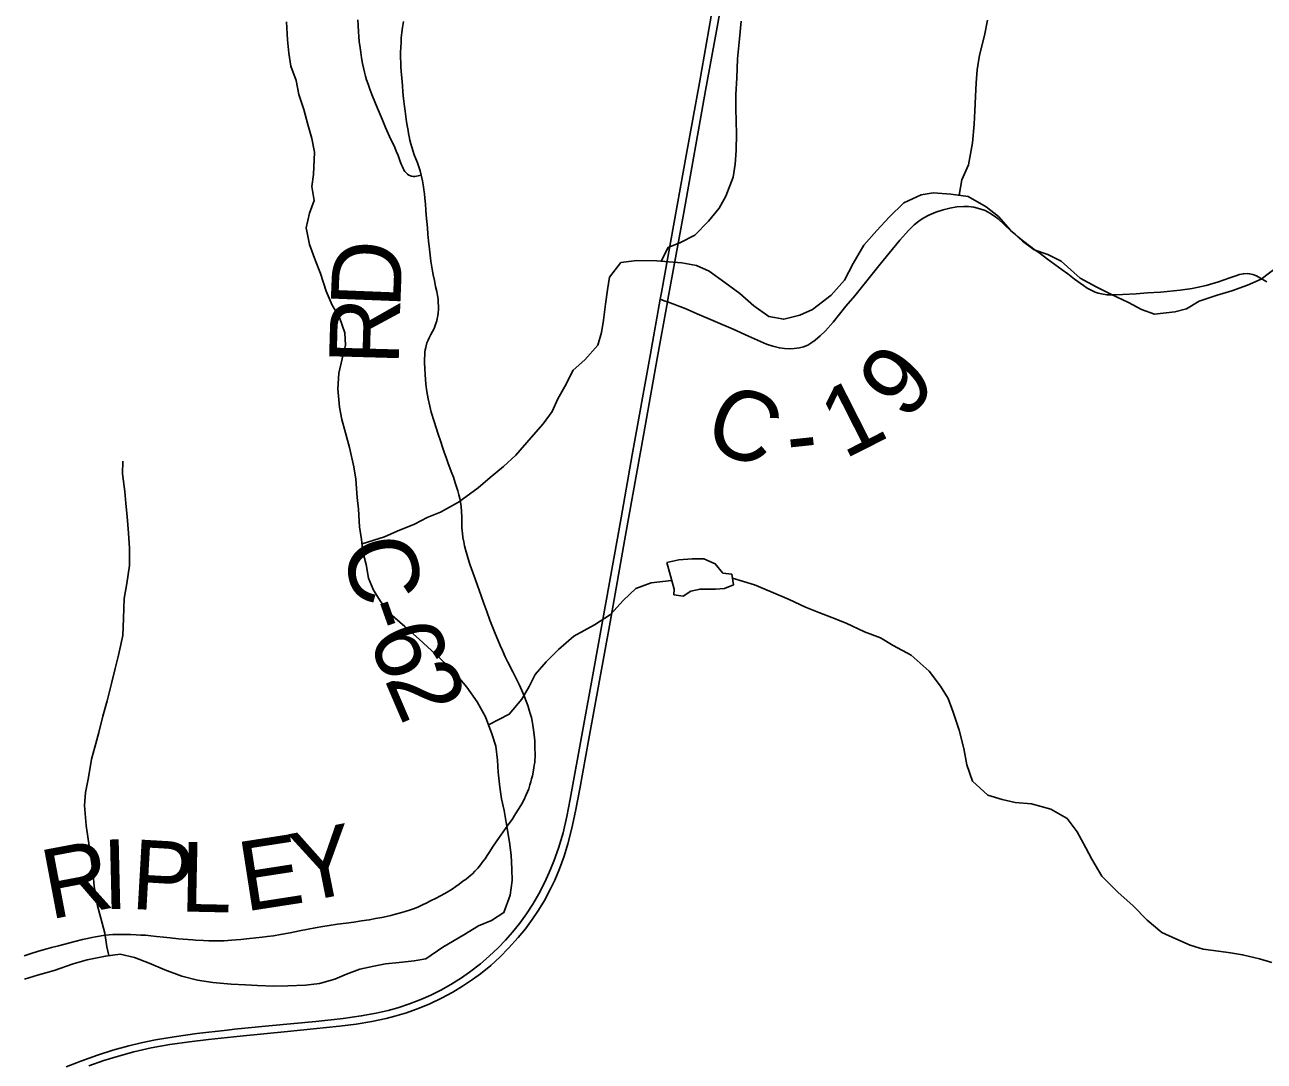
# Model space of a CAD drawing. Extents: x 0 to 34, y 0 to 22.
# Drawn here: x 6.359 to 7.37, y 18.618 to 19.464 of the extents above; entities that cross this region are included whole.
import ezdxf

# ---------------------------------------------------------------- set-up
doc = ezdxf.new("R2010")
doc.units = 0
for name, color, linetype in [('GM_X_County_Road', 7, 'Continuous'), ('GM_X_County_Road_Text', 7, 'Continuous'), ('GM_X_Minor_Lake', 7, 'Continuous'), ('GM_X_Minor_River', 7, 'Continuous'), ('GM_X_Township_Road', 7, 'Continuous'), ('GM_X_US_Route', 7, 'Continuous')]:
    doc.layers.add(name, color=color, linetype=linetype)

msp = doc.modelspace()

# ---------------------------------------------------------------- linework, layer by layer
at = {"layer": 'GM_X_County_Road'}
for points in [[(6.6827, 19.3412), (6.6818, 19.3448), (6.6808, 19.3479), (6.6796, 19.3511), (6.6783, 19.3545), (6.677, 19.3576), (6.676, 19.3605), (6.6749, 19.3639), (6.6742, 19.3668), (6.6735, 19.3696), (6.6729, 19.3726), (6.6724, 19.3751), (6.6719, 19.3776), (6.6711, 19.3816), (6.6706, 19.3847), (6.67, 19.3891), (6.6695, 19.3933), (6.669, 19.3973), (6.6683, 19.4037), (6.6678, 19.4089), (6.6673, 19.4144), (6.6668, 19.4204), (6.6664, 19.426), (6.6661, 19.4295), (6.666, 19.4329), (6.6659, 19.4371), (6.6659, 19.4414), (6.666, 19.4454), (6.6662, 19.4497), (6.6664, 19.4533), (6.6668, 19.4575), (6.6674, 19.4617), (6.6683, 19.4666)], [(6.4965, 18.7171), (6.4987, 18.7169), (6.5051, 18.7166), (6.5095, 18.7164), (6.5136, 18.7164), (6.5178, 18.7164), (6.522, 18.7165), (6.5279, 18.7169), (6.5355, 18.7175), (6.5427, 18.7182), (6.5478, 18.7188), (6.5529, 18.7193), (6.5571, 18.7199), (6.5622, 18.7206), (6.5678, 18.7215), (6.5757, 18.723), (6.5834, 18.7245), (6.5906, 18.7259), (6.5963, 18.727), (6.6025, 18.7281), (6.6075, 18.7289), (6.6145, 18.7299), (6.6216, 18.7308), (6.6277, 18.7317), (6.634, 18.7326), (6.6403, 18.7335), (6.6455, 18.7345), (6.6505, 18.7354), (6.6544, 18.7363), (6.6579, 18.7371), (6.6617, 18.7381), (6.6659, 18.7392), (6.6696, 18.7403), (6.6738, 18.7417), (6.6771, 18.7429), (6.6804, 18.7442), (6.6837, 18.7458), (6.6868, 18.7472), (6.6909, 18.7492), (6.6942, 18.7509), (6.6984, 18.7531), (6.7018, 18.755), (6.7051, 18.7569), (6.7079, 18.7586), (6.7108, 18.7607), (6.7136, 18.7626), (6.7167, 18.765), (6.7192, 18.7668), (6.7216, 18.7687), (6.7244, 18.7711), (6.7265, 18.7732), (6.7288, 18.7756), (6.7311, 18.7784), (6.733, 18.781), (6.7347, 18.7834), (6.7364, 18.7859), (6.7386, 18.7892), (6.7409, 18.7928), (6.7444, 18.798), (6.7475, 18.8026), (6.7515, 18.808), (6.7542, 18.8118), (6.7568, 18.8155), (6.7596, 18.8199), (6.7626, 18.8247), (6.7646, 18.8281), (6.7665, 18.8317), (6.7681, 18.835), (6.7694, 18.838), (6.7703, 18.8405), (6.7713, 18.8436), (6.772, 18.8461), (6.7727, 18.8485), (6.7733, 18.851), (6.774, 18.854), (6.7746, 18.8575), (6.7749, 18.8597), (6.7752, 18.862), (6.7754, 18.864), (6.7756, 18.8663), (6.7756, 18.8695), (6.7754, 18.8728), (6.7753, 18.8761), (6.7752, 18.8795), (6.7747, 18.8846), (6.7742, 18.8886), (6.7738, 18.8924), (6.7732, 18.8957), (6.7725, 18.8987), (6.7716, 18.902), (6.7708, 18.9047), (6.7698, 18.9076), (6.7687, 18.9105), (6.7677, 18.9133), (6.7665, 18.9164), (6.7648, 18.9206), (6.7626, 18.9255), (6.7604, 18.93), (6.7575, 18.936), (6.7533, 18.9437), (6.7512, 18.9482), (6.7489, 18.9532), (6.747, 18.9575), (6.7452, 18.962), (6.743, 18.9673), (6.7409, 18.9726), (6.7387, 18.9781), (6.7361, 18.9851), (6.7337, 18.9916), (6.7315, 18.9979), (6.7268, 19.0109), (6.7247, 19.017), (6.7226, 19.0229), (6.721, 19.0282), (6.7198, 19.0319), (6.7187, 19.0356), (6.718, 19.0386), (6.7173, 19.0419), (6.7167, 19.0455), (6.7164, 19.0489), (6.7159, 19.0532), (6.7158, 19.0578), (6.7157, 19.0622), (6.7155, 19.0667), (6.7152, 19.0707), (6.7146, 19.0744), (6.7141, 19.0772), (6.7133, 19.0804), (6.7124, 19.0835), (6.7115, 19.0868), (6.7104, 19.0901), (6.7089, 19.0946), (6.7077, 19.098), (6.7064, 19.1016), (6.7045, 19.1067), (6.703, 19.1109), (6.7017, 19.1143), (6.7003, 19.1183), (6.6984, 19.1243), (6.6966, 19.1297), (6.6949, 19.1349), (6.6932, 19.1402), (6.6909, 19.1478), (6.6896, 19.1526), (6.6883, 19.1587), (6.6873, 19.1647), (6.6865, 19.1707), (6.6858, 19.1786), (6.6855, 19.1834), (6.6853, 19.188), (6.6853, 19.1916), (6.6855, 19.1944), (6.6857, 19.1968), (6.6859, 19.1987), (6.6863, 19.2004), (6.6867, 19.2019), (6.6873, 19.2042), (6.6883, 19.2066), (6.6891, 19.2084), (6.6905, 19.211), (6.6919, 19.2136), (6.6931, 19.2161), (6.6941, 19.2184), (6.6947, 19.2202), (6.6953, 19.2222), (6.6957, 19.2241), (6.6961, 19.2264), (6.6965, 19.2288), (6.6967, 19.2314), (6.6968, 19.2343), (6.6966, 19.2372), (6.6964, 19.2399), (6.6959, 19.243), (6.6953, 19.2461), (6.6944, 19.2504), (6.6934, 19.2552), (6.6924, 19.2598), (6.6918, 19.2629), (6.6912, 19.2661), (6.6905, 19.271), (6.6899, 19.2758), (6.6893, 19.2807), (6.6886, 19.2876), (6.6881, 19.2929), (6.6877, 19.2981), (6.6873, 19.3032), (6.6868, 19.3084), (6.6865, 19.3127), (6.6862, 19.3175), (6.6857, 19.3223), (6.6853, 19.3258), (6.6849, 19.3291), (6.6845, 19.3315), (6.6836, 19.3366), (6.6827, 19.3412)], [(7.0642, 19.2775), (7.0729, 19.2881), (7.08, 19.2961), (7.0845, 19.3005), (7.0884, 19.3036), (7.0921, 19.3061), (7.0966, 19.3084), (7.1024, 19.3109), (7.1083, 19.3129), (7.1138, 19.3142), (7.1194, 19.3152), (7.1251, 19.3156), (7.1289, 19.3156), (7.1333, 19.315), (7.1382, 19.3137), (7.1424, 19.3122), (7.1464, 19.3102), (7.1501, 19.3078), (7.1531, 19.3054), (7.1631, 19.2961), (7.1673, 19.2926), (7.1687, 19.2914), (7.174, 19.2871), (7.1833, 19.28), (7.1873, 19.2771), (7.1933, 19.2726), (7.1963, 19.2704), (7.2023, 19.266), (7.2053, 19.2638), (7.2098, 19.2605), (7.2153, 19.2564), (7.2228, 19.251), (7.2258, 19.249), (7.2323, 19.2457), (7.2346, 19.2449), (7.2375, 19.2442), (7.2417, 19.2435), (7.2484, 19.2434), (7.2545, 19.2437), (7.2657, 19.2444), (7.275, 19.245), (7.2855, 19.2458), (7.3015, 19.2472), (7.3113, 19.2486), (7.3227, 19.2511), (7.3327, 19.2541), (7.3421, 19.2574), (7.3462, 19.2588), (7.35, 19.26), (7.3531, 19.2607), (7.3561, 19.2608), (7.3581, 19.2607), (7.3607, 19.26), (7.3638, 19.2589), (7.3666, 19.2573), (7.3721, 19.2541)], [(6.8834, 19.2378), (6.8979, 19.2323), (6.9077, 19.228), (6.937, 19.2154), (6.9495, 19.2098), (6.9642, 19.2033), (6.9694, 19.2015), (6.9747, 19.2002), (6.979, 19.1996), (6.9832, 19.1994), (6.9868, 19.1996), (6.991, 19.2003), (6.9945, 19.2012), (6.9978, 19.2025), (7.0004, 19.204), (7.0038, 19.2065), (7.008, 19.21), (7.0124, 19.2142), (7.0185, 19.2212), (7.029, 19.2342), (7.0362, 19.2427), (7.0471, 19.2563), (7.0568, 19.2684), (7.0642, 19.2775)], [(6.8776, 19.2399), (6.8809, 19.2387), (6.8834, 19.2378)], [(6.359, 18.7042), (6.3663, 18.7066), (6.3725, 18.7084), (6.3773, 18.7098), (6.3813, 18.7109), (6.3868, 18.7123), (6.4002, 18.7158), (6.4065, 18.7174), (6.4105, 18.7183), (6.4142, 18.719), (6.4171, 18.7196), (6.4203, 18.7201), (6.4247, 18.7209), (6.4281, 18.7213), (6.4312, 18.7215), (6.4349, 18.7217), (6.4384, 18.7217), (6.4423, 18.7217), (6.4456, 18.7217), (6.4502, 18.7214), (6.454, 18.7211), (6.4578, 18.7209), (6.4623, 18.7205), (6.4669, 18.72), (6.4725, 18.7193), (6.478, 18.7188), (6.4847, 18.7181), (6.4923, 18.7174), (6.4965, 18.7171)]]:
    msp.add_lwpolyline(points, dxfattribs=at)
at = {"layer": 'GM_X_Minor_Lake'}
for points in [[(6.8888, 19.0033), (6.8887, 18.9988), (6.8963, 18.9975), (6.9024, 19.0016), (6.91, 19.0034), (6.9225, 19.0033), (6.9301, 19.0039), (6.9373, 19.0068), (6.9359, 19.0156), (6.9287, 19.0164), (6.9224, 19.0241), (6.913, 19.028), (6.9035, 19.0282), (6.8928, 19.0272), (6.883, 19.025)], [(6.883, 19.025), (6.8888, 19.0033)]]:
    msp.add_lwpolyline(points, dxfattribs=at)
at = {"layer": 'GM_X_Minor_River'}
for points in [[(6.5727, 19.4662), (6.5737, 19.4517), (6.5747, 19.4407), (6.5764, 19.4301), (6.5808, 19.4183), (6.583, 19.4069)], [(6.8784, 19.2709), (6.8839, 19.2821), (6.8942, 19.2862), (6.9057, 19.2921), (6.9168, 19.3037), (6.9257, 19.3142), (6.9311, 19.324), (6.937, 19.3394), (6.9386, 19.35), (6.9395, 19.3614), (6.9397, 19.3751), (6.9394, 19.3849), (6.9392, 19.3959), (6.9393, 19.4069), (6.9399, 19.4206), (6.9405, 19.4361), (6.9422, 19.4524), (6.9435, 19.4668)], [(7.1212, 19.3247), (7.1235, 19.3373), (7.1289, 19.3497), (7.1322, 19.3675), (7.1335, 19.3827), (7.134, 19.3936), (7.1346, 19.4054), (7.1351, 19.4164), (7.136, 19.427), (7.138, 19.4391), (7.142, 19.455), (7.1444, 19.4675)], [(6.583, 19.4069), (6.587, 19.3947), (6.5902, 19.3825), (6.5935, 19.3711), (6.5956, 19.36), (6.5947, 19.3418), (6.5934, 19.332), (6.5955, 19.3206), (6.5916, 19.31), (6.5888, 19.2983), (6.5917, 19.2846), (6.5964, 19.2713), (6.6005, 19.261), (6.6052, 19.2465), (6.61, 19.2351), (6.6159, 19.2251), (6.6203, 19.2126), (6.621, 19.2023), (6.6182, 19.1913), (6.6154, 19.1796), (6.6148, 19.1667), (6.6161, 19.1519), (6.6179, 19.1417), (6.6208, 19.131), (6.6241, 19.1188), (6.6277, 19.1032), (6.6294, 19.093), (6.6304, 19.0782), (6.6314, 19.0687), (6.6324, 19.0542), (6.6341, 19.044), (6.6351, 19.0337), (6.6377, 19.0235), (6.6398, 19.0124), (6.6438, 19.0025), (6.6498, 18.993), (6.6572, 18.9834), (6.6692, 18.973), (6.6809, 18.9626), (6.6947, 18.9499), (6.7078, 18.9376), (6.7198, 18.9234), (6.7284, 18.9115), (6.735, 18.8993), (6.7402, 18.8852), (6.7435, 18.8752), (6.7448, 18.8639), (6.7455, 18.854), (6.7468, 18.8418), (6.7482, 18.8323), (6.7504, 18.8228), (6.7518, 18.8129), (6.7546, 18.797), (6.756, 18.7863), (6.7566, 18.7749), (6.7569, 18.7655), (6.7552, 18.7537), (6.7501, 18.7394), (6.7401, 18.7331), (6.7295, 18.7287), (6.7173, 18.7213), (6.7004, 18.7112), (6.6863, 18.7016), (6.6768, 18.7002), (6.6647, 18.6988), (6.6536, 18.6975), (6.6441, 18.6957), (6.6327, 18.6932), (6.6217, 18.6892), (6.6122, 18.6851), (6.5996, 18.6815), (6.5882, 18.6802), (6.5738, 18.6796), (6.5624, 18.6794), (6.5492, 18.6799), (6.5393, 18.6805), (6.5276, 18.681), (6.5128, 18.6823), (6.5003, 18.6844), (6.4875, 18.6876), (6.4735, 18.6927), (6.4607, 18.6982), (6.449, 18.7029), (6.4373, 18.7054), (6.4251, 18.704), (6.4103, 18.7008), (6.3989, 18.6975), (6.3833, 18.6921), (6.3699, 18.6884), (6.3593, 18.6852)], [(6.6345, 19.0404), (6.6527, 19.046), (6.663, 19.0508), (6.6771, 19.0563), (6.6874, 19.0618), (6.6985, 19.0662), (6.713, 19.0744), (6.729, 19.0859), (6.739, 19.0945), (6.7497, 19.1035), (6.7597, 19.1128), (6.7724, 19.127), (6.782, 19.1383), (6.7894, 19.1484), (6.794, 19.1586), (6.7999, 19.1688), (6.8065, 19.1819), (6.816, 19.1905), (6.8268, 19.2025), (6.8296, 19.2127), (6.8312, 19.2229), (6.8329, 19.2358), (6.8346, 19.2476), (6.8362, 19.2578), (6.8455, 19.2698), (6.8584, 19.2715), (6.8747, 19.2713), (6.8845, 19.2704), (6.8951, 19.2695), (6.9072, 19.2674), (6.9174, 19.2627), (6.9302, 19.2535), (6.9426, 19.2446), (6.9538, 19.2345), (6.9662, 19.2257), (6.9783, 19.2236), (6.9913, 19.2268), (7.0016, 19.2316), (7.0169, 19.2432), (7.0277, 19.2555), (7.035, 19.2691), (7.0436, 19.2841), (7.0543, 19.2961), (7.0643, 19.307), (7.0762, 19.3186), (7.0903, 19.3252), (7.1002, 19.3266), (7.1146, 19.3256), (7.1286, 19.3236), (7.1433, 19.3154), (7.1534, 19.3073), (7.1631, 19.2962), (7.1729, 19.2873), (7.1826, 19.2803), (7.1936, 19.2764), (7.2045, 19.2709), (7.2199, 19.2571), (7.2331, 19.2501), (7.2455, 19.2438), (7.2594, 19.2372), (7.27, 19.2314), (7.2806, 19.2278), (7.2973, 19.2295), (7.3068, 19.232), (7.3171, 19.2383), (7.3316, 19.2431), (7.3437, 19.2467), (7.3563, 19.2514), (7.3677, 19.2562), (7.3811, 19.2667)], [(6.4279, 18.7043), (6.4263, 18.7116), (6.4246, 18.7226), (6.4213, 18.7348), (6.4188, 18.745), (6.416, 18.7606), (6.415, 18.7739), (6.4129, 18.7868), (6.4111, 18.7994), (6.4094, 18.8104), (6.4081, 18.8267), (6.409, 18.8373), (6.4114, 18.8498), (6.4139, 18.8646), (6.4166, 18.8744), (6.4198, 18.8865), (6.423, 18.8997), (6.4266, 18.9122), (6.4302, 18.9265), (6.433, 18.9386), (6.4358, 18.9496), (6.4394, 18.9655), (6.44, 18.9795), (6.4405, 18.9958), (6.4426, 19.0079), (6.4447, 19.0227), (6.4448, 19.0367), (6.4439, 19.0489), (6.4429, 19.0625), (6.4419, 19.0732), (6.4409, 19.083), (6.4392, 19.0975), (6.4393, 19.1077)], [(6.7374, 18.8927), (6.7544, 18.9013), (6.7648, 18.9136), (6.7706, 18.9238), (6.7757, 18.9336), (6.7845, 18.9441), (6.7945, 18.9542), (6.8071, 18.965), (6.8239, 18.9743), (6.8369, 18.9828), (6.8477, 18.9944), (6.8577, 19.0038), (6.8702, 19.0085), (6.8868, 19.0105)], [(6.9364, 19.0123), (6.9544, 19.007), (6.968, 19.0011), (6.9827, 18.9948), (6.9959, 18.9886), (7.0068, 18.9843), (7.0174, 18.9803), (7.0291, 18.9756), (7.0441, 18.9686), (7.0573, 18.9635), (7.0675, 18.9573), (7.0822, 18.9495), (7.0968, 18.9364), (7.1061, 18.9241), (7.1124, 18.9142), (7.1165, 18.9031), (7.1212, 18.8883), (7.1252, 18.8734), (7.1277, 18.8601), (7.1321, 18.8468), (7.1448, 18.8352), (7.1565, 18.8317), (7.1671, 18.8292), (7.1804, 18.8283), (7.1962, 18.8239), (7.2094, 18.8162), (7.2176, 18.8054), (7.2246, 18.7924), (7.2295, 18.7829), (7.2376, 18.7691), (7.2507, 18.756), (7.2631, 18.7449), (7.2747, 18.7333), (7.2867, 18.7233), (7.298, 18.7179), (7.3097, 18.7128), (7.3203, 18.7096), (7.3328, 18.7079), (7.3426, 18.7066), (7.3524, 18.705), (7.3661, 18.7018), (7.3762, 18.6986)]]:
    msp.add_lwpolyline(points, dxfattribs=at)
at = {"layer": 'GM_X_Township_Road'}
msp.add_lwpolyline([(6.6827, 19.3412), (6.6788, 19.3403), (6.6775, 19.3401), (6.6761, 19.3401), (6.6748, 19.3403), (6.6739, 19.3406), (6.6727, 19.3411), (6.6716, 19.3419), (6.6708, 19.3425), (6.67, 19.3433), (6.6693, 19.3442), (6.6686, 19.3454), (6.6679, 19.3467), (6.6673, 19.3479), (6.6667, 19.3495), (6.6655, 19.3524), (6.6638, 19.3572), (6.6623, 19.3607), (6.6611, 19.3637), (6.6567, 19.3728), (6.6536, 19.38), (6.6509, 19.3867), (6.6468, 19.3964), (6.643, 19.4055), (6.6411, 19.4105), (6.6393, 19.4154), (6.6381, 19.419), (6.6373, 19.422), (6.6365, 19.4252), (6.6357, 19.4286), (6.6349, 19.4323), (6.6341, 19.437), (6.6335, 19.4411), (6.6329, 19.445), (6.6322, 19.4501), (6.6318, 19.4544), (6.6315, 19.4581), (6.6312, 19.4632), (6.6311, 19.468)], dxfattribs=at)
at = {"layer": 'GM_X_US_Route'}
for points in [[(6.8834, 19.2378), (6.8838, 19.2398), (6.8967, 19.3106), (6.9145, 19.4102), (6.9234, 19.459), (6.9391, 19.547), (6.9519, 19.6185), (6.9613, 19.6691), (6.9648, 19.6855), (6.9683, 19.6994), (6.9721, 19.7119), (6.9764, 19.7243), (6.9818, 19.7375), (6.9885, 19.7522), (6.996, 19.7673), (7.0027, 19.7793), (7.0075, 19.7871)], [(6.5304, 18.6442), (6.5583, 18.647), (6.5967, 18.6507), (6.619, 18.6531), (6.6338, 18.6551), (6.646, 18.6574), (6.6558, 18.6596), (6.6636, 18.6618), (6.6731, 18.6649), (6.6824, 18.6685), (6.6904, 18.672), (6.6987, 18.6762), (6.7069, 18.6808), (6.7154, 18.6862), (6.722, 18.6908), (6.7309, 18.6977), (6.738, 18.7038), (6.7453, 18.7106), (6.7514, 18.7169), (6.7572, 18.7234), (6.763, 18.7308), (6.7685, 18.7384), (6.7736, 18.7462), (6.7787, 18.7548), (6.7832, 18.7637), (6.7871, 18.7722), (6.7909, 18.7815), (6.7946, 18.7921), (6.7983, 18.8046), (6.8014, 18.8179), (6.8042, 18.832), (6.8237, 18.9395), (6.8456, 19.0616), (6.8547, 19.113), (6.8697, 19.1954), (6.8776, 19.2399), (6.8786, 19.2455), (6.8914, 19.3163), (6.8987, 19.3572), (6.9095, 19.4165), (6.9191, 19.4709)], [(6.5349, 18.6385), (6.5735, 18.6424), (6.6161, 18.6468), (6.6297, 18.6485), (6.6425, 18.6506), (6.654, 18.653), (6.6612, 18.6548), (6.6707, 18.6576), (6.6811, 18.6614), (6.6897, 18.665), (6.6992, 18.6696), (6.7084, 18.6746), (6.7164, 18.6794), (6.7246, 18.6848), (6.7311, 18.6896), (6.7393, 18.6962), (6.747, 18.7033), (6.7539, 18.7103), (6.7618, 18.7191), (6.7676, 18.7263), (6.7732, 18.7338), (6.7784, 18.7415), (6.7832, 18.7494), (6.7881, 18.7587), (6.7915, 18.7659), (6.7953, 18.7751), (6.7991, 18.7856), (6.8022, 18.7956), (6.8055, 18.8082), (6.8086, 18.8221), (6.8121, 18.8403), (6.8194, 18.8813), (6.8367, 18.9765), (6.8492, 19.0474), (6.8643, 19.1304), (6.8751, 19.1916), (6.8834, 19.2378)], [(6.3931, 18.6135), (6.4052, 18.6183), (6.4186, 18.6231), (6.4311, 18.6271), (6.4442, 18.6307), (6.4544, 18.6331), (6.466, 18.6355), (6.4813, 18.6381), (6.4997, 18.6407), (6.5244, 18.6436), (6.5304, 18.6442)], [(6.4115, 18.6144), (6.4239, 18.6187), (6.4358, 18.6224), (6.4484, 18.6258), (6.4624, 18.629), (6.4777, 18.6317), (6.4937, 18.634), (6.5092, 18.6359), (6.5349, 18.6385)]]:
    msp.add_lwpolyline(points, dxfattribs=at)

# ---------------------------------------------------------------- texts
at = {"layer": 'GM_X_County_Road_Text'}
for s, rotation, p in [('D', 87.7153, (6.6655, 19.232)), ('R', 88.3918, (6.6642, 19.1856)), ('9', 48.8971, (7.0776, 19.1393)), ('C', 339.19, (6.9107, 19.1204)), ('1', 26.8876, (7.0276, 19.109)), ('-', 6.0436, (6.9829, 19.1001)), ('C', 283.508, (6.6177, 19.0397)), ('-', 289.605, (6.6305, 18.988)), ('6', 291.2802, (6.6389, 18.9644)), ('2', 293.2138, (6.6524, 18.9298)), ('Y', 11.2455, (6.5834, 18.7472)), ('I', 1.331, (6.4232, 18.7421)), ('P', 356.7494, (6.4453, 18.7426)), ('E', 8.8257, (6.5389, 18.7402)), ('R', 10.7232, (6.3797, 18.7337)), ('L', 358.7784, (6.4857, 18.7404))]:
    msp.add_text(s, height=0.0568, rotation=rotation, dxfattribs=at).set_placement(p)

doc.saveas('drawing.dxf')
